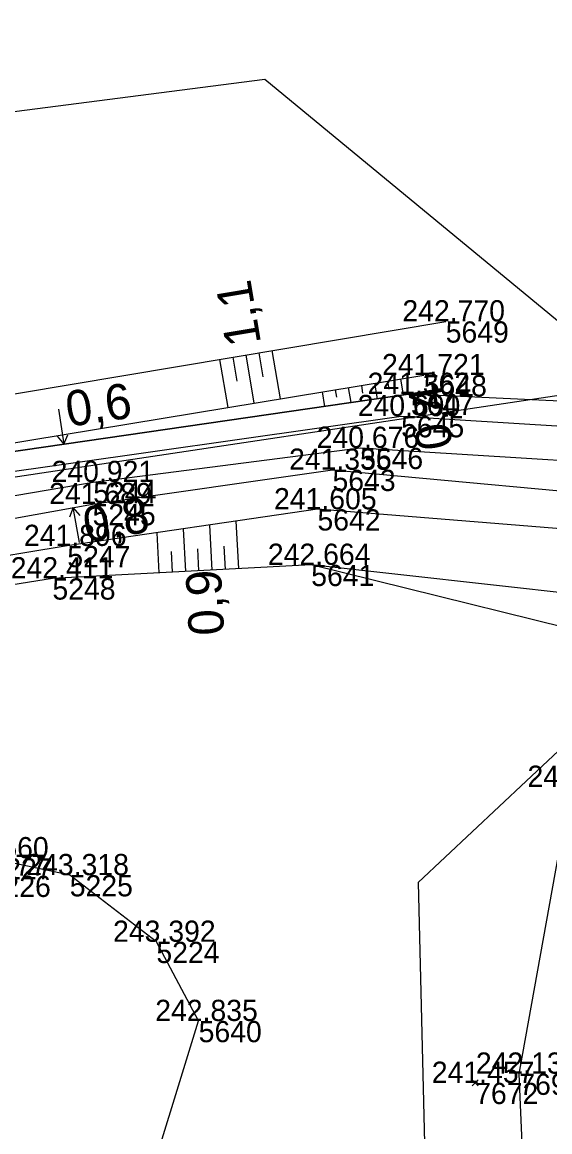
# Model space of a CAD drawing. Extents: x -809970 to -809480, y -1011362 to -1010672.
# Drawn here: x -809842.7 to -809812.8, y -1010891.5 to -1010828.7 of the extents above; entities that cross this region are included whole.
import ezdxf

# ---------------------------------------------------------------- set-up
doc = ezdxf.new("R2010")
doc.units = 0
for name, color, linetype in [('Vrstva 13', 7, 'Continuous'), ('Vrstva 17', 7, 'Continuous'), ('Vrstva 18', 7, 'Continuous'), ('Vrstva 48', 7, 'Continuous'), ('Vrstva 49', 7, 'Continuous'), ('Vrstva 50', 7, 'Continuous'), ('Vrstva 53', 7, 'Continuous'), ('Vrstva 60', 7, 'Continuous'), ('Vrstva 61', 7, 'Continuous')]:
    doc.layers.add(name, color=color, linetype=linetype)

msp = doc.modelspace()

# ---------------------------------------------------------------- linework, layer by layer
at = {"layer": 'Vrstva 13'}
for p, q in [((-809840.606, -1010850.61), (-809840.318, -1010852.589)), ((-809839.422, -1010858.14), (-809839.778, -1010856.172))]:
    msp.add_line(p, q, dxfattribs=at)
for points in [[(-809898.022, -1010866.966), (-809878.967, -1010859.295), (-809872.348, -1010857.617), (-809867.956, -1010856.6), (-809820.688, -1010849.74), (-809797.365, -1010850.83), (-809788.174, -1010847.963), (-809775.64, -1010842.536)], [(-809898.383, -1010868.528), (-809878.324, -1010860.125), (-809872.074, -1010858.406), (-809867.894, -1010857.642), (-809821.241, -1010850.996), (-809799.391, -1010852.357), (-809792.078, -1010851.44), (-809784.768, -1010848.893)], [(-809898.225, -1010870.023), (-809885.881, -1010864.684), (-809874.417, -1010861.27), (-809865.77, -1010859.37), (-809858.593, -1010858.13), (-809838.647, -1010854.725), (-809823.564, -1010852.793), (-809801.714, -1010854.154), (-809794.401, -1010853.237), (-809787.091, -1010850.69)], [(-809840.687, -1010852.137), (-809840.318, -1010852.589), (-809840.093, -1010852.051)], [(-809895.523, -1010870.311), (-809884.625, -1010865.27), (-809874.481, -1010862.397), (-809857.419, -1010859.362), (-809838.687, -1010855.975), (-809825.119, -1010854.033), (-809805.911, -1010855.815), (-809792.375, -1010854.686)], [(-809839.393, -1010856.611), (-809839.778, -1010856.172), (-809839.984, -1010856.718)]]:
    msp.add_lwpolyline(points, dxfattribs=at)
at = {"layer": 'Vrstva 17'}
msp.add_lwpolyline([(-809816.368, -1010956.508), (-809815.855, -1010953.161), (-809816.885, -1010937.943), (-809817.019, -1010930.187), (-809812.79, -1010929.244), (-809814.558, -1010888.198), (-809811.641, -1010871.97), (-809791.356, -1010869.614)], dxfattribs=at)
at = {"layer": 'Vrstva 18'}
msp.add_line((-809745.836, -1010839.815), (-809860.353, -1010857.055), dxfattribs=at)
at = {"layer": 'Vrstva 48'}
for p, q in [((-809831.501, -1010847.784), (-809831.044, -1010850.507)), ((-809830.761, -1010847.66), (-809830.532, -1010849.022)), ((-809830.021, -1010847.535), (-809829.564, -1010850.262)), ((-809829.282, -1010847.411), (-809829.053, -1010848.776)), ((-809828.542, -1010847.287), (-809828.084, -1010850.018)), ((-809822.008, -1010849.015), (-809821.934, -1010849.463)), ((-809821.268, -1010848.893), (-809821.118, -1010849.802)), ((-809825.708, -1010849.626), (-809825.572, -1010850.449)), ((-809824.968, -1010849.504), (-809824.899, -1010849.922)), ((-809824.228, -1010849.382), (-809824.087, -1010850.233)), ((-809823.488, -1010849.26), (-809823.416, -1010849.693)), ((-809822.748, -1010849.137), (-809822.602, -1010850.018)), ((-809831.921, -1010859.704), (-809832.054, -1010857.161)), ((-809830.423, -1010859.626), (-809830.563, -1010856.942)), ((-809834.916, -1010859.861), (-809835.035, -1010857.598)), ((-809833.419, -1010859.782), (-809833.544, -1010857.379)), ((-809831.172, -1010859.665), (-809831.24, -1010858.358)), ((-809834.168, -1010859.822), (-809834.229, -1010858.655)), ((-809832.67, -1010859.743), (-809832.734, -1010858.507))]:
    msp.add_line(p, q, dxfattribs=at)
at = {"layer": 'Vrstva 49'}
for p, q in [((-809867.956, -1010856.6), (-809819.959, -1010848.677)), ((-809817.229, -1010888.54), (-809816.875, -1010888.894)), ((-809817.229, -1010888.894), (-809816.875, -1010888.54))]:
    msp.add_line(p, q, dxfattribs=at)
for points in [[(-809899.66, -1010865.073), (-809880.506, -1010856.561), (-809872.832, -1010855.121), (-809866.076, -1010853.386), (-809861.095, -1010852.751), (-809818.717, -1010845.638)], [(-809820.688, -1010849.74), (-809867.956, -1010856.6), (-809872.348, -1010857.617), (-809878.967, -1010859.295), (-809898.022, -1010866.966)], [(-809791.033, -1010856.859), (-809806.166, -1010857.867), (-809825.97, -1010856.269), (-809840.115, -1010858.342), (-809856.784, -1010861.08), (-809874.481, -1010862.397), (-809884.625, -1010865.27), (-809895.523, -1010870.311)], [(-809788.574, -1010859.014), (-809806.036, -1010861.679), (-809826.323, -1010859.411), (-809840.957, -1010860.177), (-809855.712, -1010862.538), (-809858.569, -1010861.917), (-809859.807, -1010861.343), (-809864.88, -1010862.159), (-809868.608, -1010862.714), (-809873.882, -1010863.221), (-809883.301, -1010866.227), (-809893.783, -1010870.477)], [(-809787.12, -1010861.674), (-809806.523, -1010864.319), (-809826.323, -1010859.411)], [(-809824.923, -1010977.248), (-809832.146, -1010953.133), (-809837.944, -1010921.765), (-809839.29, -1010906.656), (-809832.688, -1010885.218), (-809835.079, -1010880.738), (-809839.978, -1010876.967), (-809844.518, -1010876.01), (-809844.618, -1010877), (-809856.883, -1010875.823)]]:
    msp.add_lwpolyline(points, dxfattribs=at)
at = {"layer": 'Vrstva 50'}
for points in [[(-809898.383, -1010868.528), (-809878.324, -1010860.125), (-809872.074, -1010858.406), (-809867.894, -1010857.642), (-809821.241, -1010850.996), (-809799.391, -1010852.357), (-809792.078, -1010851.44), (-809784.768, -1010848.893)], [(-809898.225, -1010870.023), (-809885.881, -1010864.684), (-809874.417, -1010861.27), (-809865.77, -1010859.37), (-809858.593, -1010858.13), (-809838.647, -1010854.725), (-809823.564, -1010852.793), (-809801.714, -1010854.154), (-809794.401, -1010853.237), (-809787.091, -1010850.69)]]:
    msp.add_lwpolyline(points, dxfattribs=at)
at = {"layer": 'Vrstva 53'}
msp.add_lwpolyline([(-809848.47, -1010824.63), (-809848.99, -1010834.52), (-809828.94, -1010831.94), (-809811.76, -1010846.11), (-809806.99, -1010849.89), (-809798.33, -1010856.76), (-809803.49, -1010861.61), (-809820.27, -1010877.38), (-809819.54, -1010907.65), (-809817.34, -1010954.54), (-809819.55, -1010971.19), (-809826.87, -1010981.55), (-809825.08, -1010988.69), (-809823.59, -1010994.66), (-809817.83, -1011024.91), (-809805.06, -1011048.21)], dxfattribs=at)
at = {"layer": 'Vrstva 60'}
for p, q in [((-809818.717, -1010845.638), (-809818.717, -1010845.638)), ((-809819.959, -1010848.677), (-809819.959, -1010848.677)), ((-809820.688, -1010849.74), (-809820.688, -1010849.74)), ((-809821.241, -1010850.996), (-809821.241, -1010850.996)), ((-809823.564, -1010852.793), (-809823.564, -1010852.793)), ((-809825.119, -1010854.033), (-809825.119, -1010854.033)), ((-809838.647, -1010854.725), (-809838.647, -1010854.725)), ((-809838.687, -1010855.975), (-809838.687, -1010855.975)), ((-809825.97, -1010856.269), (-809825.97, -1010856.269)), ((-809840.115, -1010858.342), (-809840.115, -1010858.342)), ((-809826.323, -1010859.411), (-809826.323, -1010859.411)), ((-809840.957, -1010860.177), (-809840.957, -1010860.177)), ((-809839.978, -1010876.967), (-809839.978, -1010876.967)), ((-809835.079, -1010880.738), (-809835.079, -1010880.738)), ((-809832.688, -1010885.218), (-809832.688, -1010885.218)), ((-809814.558, -1010888.198), (-809814.558, -1010888.198)), ((-809817.052, -1010888.717), (-809817.052, -1010888.717))]:
    msp.add_line(p, q, dxfattribs=at)

# ---------------------------------------------------------------- texts
at = {"layer": 'Vrstva 13'}
for s, rotation, p in [('0,6', 8.25768, (-809840.052, -1010851.606)), ('0,8', 10.24912, (-809839.018, -1010858.168))]:
    msp.add_text(s, height=2, rotation=rotation, dxfattribs=at).set_placement(p)
at = {"layer": 'Vrstva 48'}
for s, rotation, p in [('1,1', 99.52808, (-809829.154, -1010846.864)), ('0,4', 99.37345, (-809818.299, -1010852.727)), ('0,9', 92.99635, (-809831.239, -1010863.356))]:
    msp.add_text(s, height=2, rotation=rotation, dxfattribs=at).set_placement(p)
at = {"layer": 'Vrstva 60'}
for s, p in [('5649', (-809818.717, -1010846.838)), ('5648', (-809819.959, -1010849.877)), ('5647', (-809820.688, -1010850.94)), ('5645', (-809821.241, -1010852.196)), ('5646', (-809823.564, -1010853.993)), ('5643', (-809825.119, -1010855.233)), ('5244', (-809838.647, -1010855.925)), ('5245', (-809838.687, -1010857.175)), ('5642', (-809825.97, -1010857.469)), ('5247', (-809840.115, -1010859.542)), ('5641', (-809826.323, -1010860.611)), ('5248', (-809840.957, -1010861.377)), ('5227', (-809844.518, -1010877.21)), ('5226', (-809844.618, -1010878.2)), ('5225', (-809839.978, -1010878.167)), ('5224', (-809835.079, -1010881.938)), ('5640', (-809832.688, -1010886.418)), ('7695', (-809814.558, -1010889.398)), ('7672', (-809817.052, -1010889.917))]:
    msp.add_text(s, height=1.2, dxfattribs=at).set_placement(p)
at = {"layer": 'Vrstva 61'}
for s, p in [('242.770', (-809821.168, -1010845.638)), ('241.721', (-809822.316, -1010848.677)), ('241.362', (-809823.136, -1010849.74)), ('240.690', (-809823.692, -1010850.996)), ('240.676', (-809826.016, -1010852.793)), ('241.335', (-809827.575, -1010854.033)), ('240.921', (-809841.004, -1010854.725)), ('241.689', (-809841.141, -1010855.975)), ('241.605', (-809828.426, -1010856.269)), ('241.896', (-809842.567, -1010858.342)), ('242.664', (-809828.774, -1010859.411)), ('242.411', (-809843.314, -1010860.177)), ('241.550', (-809814.092, -1010871.97)), ('243.560', (-809846.969, -1010876.01)), ('243.677', (-809847.07, -1010877)), ('243.318', (-809842.432, -1010876.967)), ('243.392', (-809837.527, -1010880.738)), ('242.835', (-809835.144, -1010885.218)), ('242.138', (-809817.012, -1010888.198)), ('241.457', (-809819.504, -1010888.717))]:
    msp.add_text(s, height=1.2, dxfattribs=at).set_placement(p)

doc.saveas('drawing.dxf')
